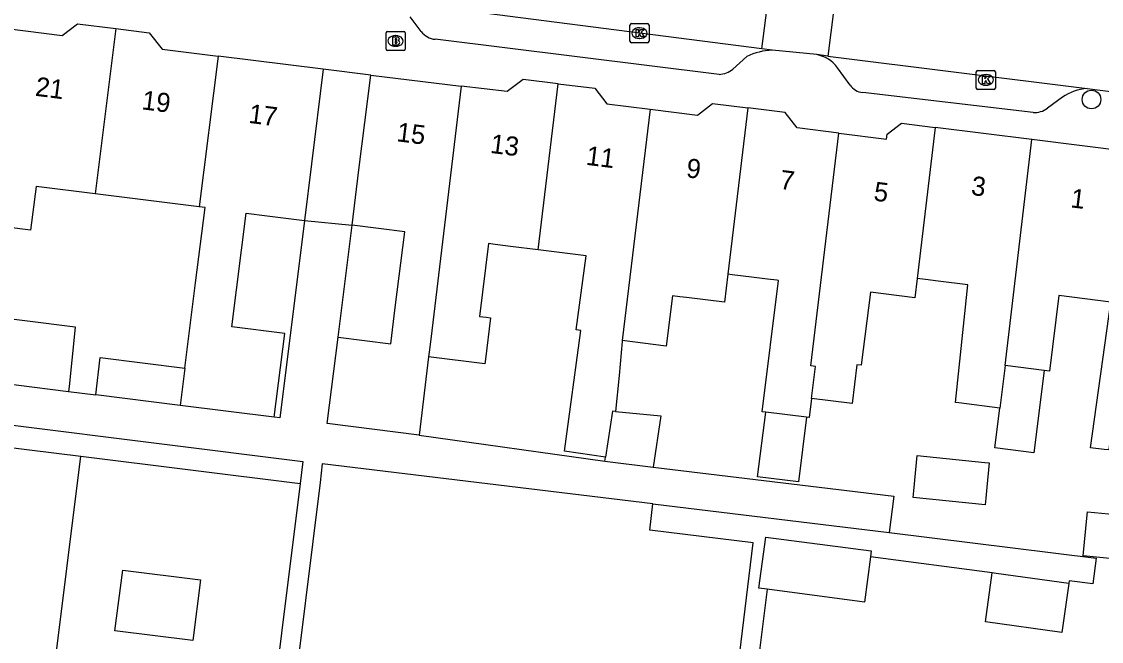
# Model space of a CAD drawing. Extents: x 161696 to 162377, y 380761 to 381673.
# Drawn here: x 162038 to 162094.7, y 381365 to 381397.5 of the extents above; entities that cross this region are included whole.
import ezdxf

# ---------------------------------------------------------------- set-up
doc = ezdxf.new("R2010")
doc.units = 0
for name, color, linetype in [('IMGEO_Boom', 7, 'Continuous'), ('IMGEO_Brandkraan', 7, 'Continuous'), ('IMGEO_Kolk', 7, 'Continuous'), ('IMGEO_Pand', 7, 'Continuous'), ('IMGEO_Pand_nummerreeks', 7, 'Continuous'), ('IMGEO_Pand_overbouw', 7, 'Continuous'), ('IMGEO_Rijbaan_lokaal_open', 7, 'Continuous'), ('IMGEO_Voetpad_open', 7, 'Continuous')]:
    doc.layers.add(name, color=color, linetype=linetype)

msp = doc.modelspace()

# ---------------------------------------------------------------- linework, layer by layer
at = {"layer": 'IMGEO_Boom'}
msp.add_circle((162094.154, 381393.439), 0.489, dxfattribs=at)
at = {"layer": 'IMGEO_Brandkraan'}
for p, q in [((162057.206, 381397.009), (162058.058, 381397.009)), ((162057.131, 381396.083), (162057.131, 381396.935)), ((162057.619, 381396.789), (162057.644, 381396.789)), ((162058.132, 381396.935), (162058.132, 381396.083)), ((162058.058, 381396.009), (162057.206, 381396.009)), ((162057.642, 381396.229), (162057.617, 381396.229))]:
    msp.add_line(p, q, dxfattribs=at)
for points in [[(162057.206, 381397.009), (162058.058, 381397.009)], [(162057.131, 381396.083), (162057.131, 381396.935)], [(162057.479, 381396.709), (162057.479, 381396.309), (162057.692, 381396.309)], [(162057.71, 381396.709), (162057.479, 381396.709)], [(162057.658, 381396.628), (162057.604, 381396.628), (162057.604, 381396.552)], [(162057.604, 381396.552), (162057.657, 381396.552)], [(162057.666, 381396.476), (162057.604, 381396.476), (162057.604, 381396.395)], [(162058.132, 381396.935), (162058.132, 381396.083)], [(162058.058, 381396.009), (162057.206, 381396.009)], [(162057.604, 381396.395), (162057.666, 381396.395)]]:
    msp.add_lwpolyline(points, dxfattribs=at)
for centre, radius, start, end in [((162057.208, 381396.933), 0.0765, 91.552, 178.448), ((162057.208, 381396.933), 0.0765, 91.552, 178.448), ((162058.056, 381396.933), 0.0765, 1.552, 88.448), ((162058.056, 381396.933), 0.0765, 1.552, 88.448), ((162057.659, 381396.59), 0.0379, 267.8285, 90.9355), ((162057.667, 381396.435), 0.0404, 269.8759, 90.5077), ((162057.714, 381396.564), 0.145, 59.4692, 91.5367), ((162057.739, 381396.611), 0.0922, 285.5137, 58.1501), ((162057.744, 381396.419), 0.105, 301.3115, 78.989), ((162057.208, 381396.085), 0.0765, 181.552, 268.448), ((162057.208, 381396.085), 0.0765, 181.552, 268.448), ((162057.698, 381396.56), 0.251, 268.6676, 293.5347), ((162058.056, 381396.085), 0.0765, 271.552, 358.448), ((162058.056, 381396.085), 0.0765, 271.552, 358.448)]:
    msp.add_arc(centre, radius, start, end, dxfattribs=at)
for centre, major_axis, ratio, start_param, end_param in [((162057.618, 381396.509), (-0.387, 0.002), 0.722429, 4.712389, 7.853982), ((162057.643, 381396.509), (-0.39, 0.002), 0.717154, 1.570796, 4.712389)]:
    msp.add_ellipse(centre, major_axis=major_axis, ratio=ratio, start_param=start_param, end_param=end_param, dxfattribs=at)
at = {"layer": 'IMGEO_Kolk'}
for p, q in [((162069.932, 381396.494), (162069.932, 381397.346)), ((162070.007, 381397.42), (162070.859, 381397.42)), ((162070.42, 381397.2), (162070.445, 381397.2)), ((162070.933, 381397.346), (162070.933, 381396.494)), ((162070.859, 381396.42), (162070.007, 381396.42)), ((162070.443, 381396.64), (162070.418, 381396.64)), ((162088.108, 381394.041), (162088.108, 381394.893)), ((162088.183, 381394.967), (162089.035, 381394.967)), ((162088.596, 381394.747), (162088.621, 381394.747)), ((162089.109, 381394.893), (162089.109, 381394.041)), ((162088.619, 381394.187), (162088.594, 381394.187)), ((162089.035, 381393.967), (162088.183, 381393.967))]:
    msp.add_line(p, q, dxfattribs=at)
for points in [[(162069.932, 381396.494), (162069.932, 381397.346)], [(162070.007, 381397.42), (162070.859, 381397.42)], [(162070.253, 381397.12), (162070.376, 381397.12), (162070.376, 381396.969), (162070.506, 381397.12), (162070.67, 381397.12), (162070.524, 381396.969), (162070.677, 381396.72), (162070.525, 381396.72), (162070.44, 381396.884), (162070.376, 381396.817), (162070.376, 381396.72), (162070.253, 381396.72), (162070.253, 381397.12)], [(162070.933, 381397.346), (162070.933, 381396.494)], [(162070.859, 381396.42), (162070.007, 381396.42)], [(162088.108, 381394.041), (162088.108, 381394.893)], [(162088.183, 381394.967), (162089.035, 381394.967)], [(162089.109, 381394.893), (162089.109, 381394.041)], [(162088.429, 381394.667), (162088.552, 381394.667), (162088.552, 381394.516), (162088.682, 381394.667), (162088.846, 381394.667), (162088.7, 381394.516), (162088.853, 381394.267), (162088.701, 381394.267), (162088.616, 381394.431), (162088.552, 381394.364), (162088.552, 381394.267), (162088.429, 381394.267), (162088.429, 381394.667)], [(162089.035, 381393.967), (162088.183, 381393.967)]]:
    msp.add_lwpolyline(points, dxfattribs=at)
for centre, start, end in [((162070.009, 381397.344), 91.552, 178.448), ((162070.009, 381397.344), 91.552, 178.448), ((162070.857, 381397.344), 1.552, 88.448), ((162070.857, 381397.344), 1.552, 88.448), ((162070.009, 381396.496), 181.552, 268.448), ((162070.009, 381396.496), 181.552, 268.448), ((162070.857, 381396.496), 271.552, 358.448), ((162070.857, 381396.496), 271.552, 358.448), ((162088.185, 381394.891), 91.552, 178.448), ((162088.185, 381394.891), 91.552, 178.448), ((162089.033, 381394.891), 1.552, 88.448), ((162089.033, 381394.891), 1.552, 88.448), ((162088.185, 381394.043), 181.552, 268.448), ((162088.185, 381394.043), 181.552, 268.448), ((162089.033, 381394.043), 271.552, 358.448), ((162089.033, 381394.043), 271.552, 358.448)]:
    msp.add_arc(centre, 0.0765, start, end, dxfattribs=at)
for centre, major_axis, ratio, start_param, end_param in [((162070.419, 381396.92), (-0.387, 0.002), 0.722429, 4.712389, 7.853982), ((162070.444, 381396.92), (-0.39, 0.002), 0.717154, 1.570796, 4.712389), ((162088.595, 381394.467), (-0.387, 0.002), 0.722429, 4.712389, 7.853982), ((162088.62, 381394.467), (-0.39, 0.002), 0.717154, 1.570796, 4.712389)]:
    msp.add_ellipse(centre, major_axis=major_axis, ratio=ratio, start_param=start_param, end_param=end_param, dxfattribs=at)
at = {"layer": 'IMGEO_Pand'}
for points in [[(162037.258, 381397.157), (162040.14, 381396.796), (162040.934, 381397.414), (162042.957, 381397.161)], [(162042.957, 381397.161), (162041.873, 381388.497)], [(162042.957, 381397.161), (162044.707, 381396.942), (162045.375, 381396.083), (162048.318, 381395.715)], [(162048.318, 381395.715), (162047.329, 381387.815)], [(162053.837, 381395.025), (162048.318, 381395.715)], [(162053.837, 381395.025), (162053.217, 381390.064), (162052.846, 381387.092)], [(162055.349, 381386.844), (162055.712, 381389.749), (162056.334, 381394.724)], [(162056.334, 381394.724), (162061.073, 381394.148)], [(162061.073, 381394.148), (162059.478, 381380.88), (162059.395, 381380.187), (162059.366, 381379.944)], [(162066.17, 381394.266), (162064.325, 381394.497), (162063.497, 381393.853), (162061.073, 381394.148)], [(162065.123, 381385.556), (162066.17, 381394.266)], [(162066.17, 381394.266), (162068.087, 381394.027), (162068.721, 381393.212), (162070.989, 381392.928)], [(162070.989, 381392.928), (162073.477, 381392.617), (162074.272, 381393.236), (162076.123, 381393.005)], [(162076.123, 381393.005), (162075.075, 381384.281)], [(162080.896, 381391.674), (162078.704, 381391.948), (162078.072, 381392.761), (162076.123, 381393.005)], [(162070.989, 381392.928), (162069.531, 381380.796)], [(162080.896, 381391.674), (162083.4, 381391.361), (162083.433, 381391.621), (162084.178, 381392.2), (162085.954, 381391.978)], [(162085.954, 381391.978), (162085.002, 381384.057)], [(162091.014, 381391.346), (162085.954, 381391.978)], [(162079.463, 381377.766), (162079.664, 381379.438), (162079.429, 381379.468), (162080.896, 381391.674)], [(162089.615, 381379.488), (162091.014, 381391.346)], [(162096.159, 381390.703), (162091.014, 381391.346)], [(162041.873, 381388.497), (162038.763, 381388.886), (162038.476, 381386.593), (162035.975, 381386.905)], [(162047.329, 381387.815), (162041.873, 381388.497)], [(162046.578, 381379.349), (162047.138, 381383.826), (162047.632, 381387.777), (162047.329, 381387.815)], [(162051.269, 381376.783), (162051.817, 381381.17), (162049.04, 381381.518), (162049.785, 381387.474), (162050.065, 381387.439), (162050.622, 381387.37), (162052.846, 381387.092)], [(162054.615, 381380.971), (162057.377, 381380.626), (162057.615, 381382.534), (162058.11, 381386.499), (162055.349, 381386.844)], [(162065.123, 381385.556), (162063.658, 381385.739), (162062.866, 381385.838), (162062.508, 381385.883), (162062.03, 381382.063), (162062.389, 381382.018), (162062.617, 381381.99), (162062.345, 381379.818), (162062.315, 381379.575), (162059.366, 381379.944)], [(162068.648, 381374.686), (162066.5, 381374.99), (162067.356, 381381.329), (162067.108, 381381.362), (162067.631, 381385.243), (162065.123, 381385.556)], [(162075.075, 381384.281), (162074.898, 381382.806), (162072.902, 381383.055), (162072.542, 381383.1), (162072.17, 381383.146), (162071.839, 381380.507), (162069.531, 381380.796)], [(162077.057, 381377.042), (162076.872, 381377.065), (162077.734, 381383.949), (162077.648, 381383.96), (162077.156, 381384.021), (162076.306, 381384.127), (162075.302, 381384.253), (162075.075, 381384.281)], [(162085.002, 381384.057), (162084.88, 381383.044), (162082.549, 381383.335), (162082.07, 381379.502), (162081.844, 381379.53), (162081.59, 381377.5), (162079.463, 381377.766)], [(162089.337, 381377.258), (162087.19, 381377.526), (162087.011, 381377.548), (162087.657, 381383.726), (162086.102, 381383.92), (162085.446, 381384.002), (162085.002, 381384.057)], [(162095.173, 381382.813), (162092.436, 381383.155), (162091.941, 381379.198), (162091.666, 381379.232)], [(162035.369, 381382.094), (162035.381, 381382.2), (162040.822, 381381.513), (162040.79, 381381.146), (162040.496, 381378.382), (162040.469, 381378.131)], [(162058.873, 381375.843), (162054.049, 381376.446), (162054.615, 381380.971)], [(162069.531, 381380.796), (162069.526, 381380.753), (162069.358, 381378.97), (162069.175, 381377.081)], [(162041.894, 381377.954), (162042.137, 381379.904), (162046.578, 381379.349)], [(162059.366, 381379.944), (162058.873, 381375.843)], [(162089.615, 381379.488), (162089.337, 381377.258)], [(162091.666, 381379.232), (162089.615, 381379.488)], [(162046.578, 381379.349), (162046.334, 381377.399)], [(162091.666, 381379.232), (162091.127, 381374.909), (162089.076, 381375.166), (162089.337, 381377.258)], [(162034.963, 381378.819), (162040.469, 381378.131)], [(162046.334, 381377.399), (162041.894, 381377.954)], [(162079.463, 381377.766), (162079.338, 381376.757), (162079.2, 381376.774)], [(162051.269, 381376.783), (162046.334, 381377.399)], [(162069.175, 381377.081), (162069.008, 381377.097), (162068.648, 381374.686)], [(162069.175, 381377.081), (162071.545, 381376.858), (162071.151, 381374.15)], [(162079.2, 381376.774), (162078.776, 381373.384), (162076.633, 381373.652), (162077.057, 381377.042)], [(162079.2, 381376.774), (162077.057, 381377.042)], [(162034.803, 381369.197), (162035.577, 381375.42), (162041.121, 381374.73)], [(162038.184, 381351.173), (162041.121, 381374.73)], [(162041.121, 381374.73), (162052.623, 381373.299)], [(162068.615, 381374.467), (162068.648, 381374.686)], [(162068.615, 381374.467), (162071.151, 381374.15)], [(162088.553, 381374.412), (162088.79, 381374.388), (162088.661, 381373.107), (162088.603, 381372.529), (162088.568, 381372.189), (162084.79, 381372.569), (162084.824, 381372.91), (162085.012, 381374.77), (162088.553, 381374.412)], [(162052.623, 381373.299), (162050.669, 381357.597), (162050.309, 381354.704), (162049.692, 381349.742)], [(162096.886, 381371.529), (162096.852, 381371.178), (162096.818, 381370.826), (162096.663, 381369.223), (162096.528, 381369.236), (162093.712, 381369.509), (162093.92, 381371.655), (162093.935, 381371.815), (162096.886, 381371.529)], [(162077.135, 381367.757), (162076.704, 381367.814), (162077.055, 381370.489), (162082.588, 381369.763), (162082.547, 381369.454)], [(162082.547, 381369.454), (162082.237, 381367.087), (162077.135, 381367.757)], [(162047.399, 381368.243), (162046.995, 381365.06), (162042.893, 381365.569), (162043.312, 381368.754), (162047.399, 381368.243)], [(162092.955, 381368.064), (162092.6, 381365.486), (162088.584, 381366.04), (162088.939, 381368.617)], [(162092.955, 381368.064), (162089.151, 381368.588), (162088.939, 381368.617)]]:
    msp.add_lwpolyline(points, dxfattribs=at)
at = {"layer": 'IMGEO_Pand_overbouw'}
msp.add_lwpolyline([(162056.334, 381394.724), (162053.837, 381395.025), (162053.217, 381390.064), (162052.846, 381387.092), (162055.349, 381386.844), (162055.712, 381389.749)], close=True, dxfattribs=at)
at = {"layer": 'IMGEO_Rijbaan_lokaal_open'}
for points in [[(162076.85, 381396.098), (162077.323, 381399.762)], [(162080.767, 381399.306), (162080.312, 381395.719)], [(162076.85, 381396.098), (162057.242, 381398.61)], [(162077.396, 381396.028), (162076.85, 381396.098)], [(162079.731, 381395.792), (162077.396, 381396.028)], [(162080.312, 381395.719), (162079.731, 381395.792)], [(162080.312, 381395.719), (162093.918, 381394.013)], [(162093.918, 381394.013), (162096.927, 381393.631)]]:
    msp.add_lwpolyline(points, dxfattribs=at)
at = {"layer": 'IMGEO_Voetpad_open'}
for points in [[(162058.983, 381397), (162058.392, 381397.782)], [(162074.61, 381394.751), (162059.711, 381396.598)], [(162076.066, 381395.693), (162075.336, 381395.039)], [(162056.334, 381394.724), (162053.837, 381395.025)], [(162081.486, 381394.196), (162080.823, 381395.107)], [(162091.084, 381392.754), (162082.146, 381393.802)], [(162092.628, 381393.562), (162091.845, 381392.98)], [(162052.846, 381387.092), (162052.128, 381381.351), (162051.552, 381376.748), (162051.269, 381376.783)], [(162054.615, 381380.971), (162055.349, 381386.844)], [(162095.86, 381381.582), (162095.063, 381375.06), (162094.826, 381375.089), (162094.098, 381375.165), (162095.173, 381382.813)], [(162040.469, 381378.131), (162041.894, 381377.954)], [(162029.846, 381377.326), (162052.767, 381374.449), (162052.623, 381373.299)], [(162058.873, 381375.843), (162068.615, 381374.467)], [(162071.138, 381372.231), (162053.786, 381374.326), (162053.669, 381373.359), (162052.113, 381360.842), (162052.1, 381360.737)], [(162071.151, 381374.15), (162083.774, 381372.644), (162083.528, 381370.735)], [(162074.51, 381354.62), (162076.391, 381370.198), (162070.971, 381370.852), (162071.138, 381372.231)], [(162071.138, 381372.231), (162083.528, 381370.735)], [(162083.528, 381370.735), (162094.392, 381369.392), (162094.229, 381368.044), (162092.973, 381368.195), (162092.955, 381368.064)], [(162088.939, 381368.617), (162082.547, 381369.454)], [(162077.135, 381367.757), (162076.421, 381362.024)]]:
    msp.add_lwpolyline(points, dxfattribs=at)
for centre, radius, start, end in [((162059.783, 381397.588), 0.992, 216.3241, 265.8611), ((162077.525, 381392.708), 3.322, 92.2252, 116.0499), ((162079.433, 381394.104), 1.714, 35.8083, 79.9925), ((162074.541, 381395.985), 1.236, 273.217, 310.0589), ((162082.238, 381394.706), 0.909, 214.1554, 264.1728), ((162094.14, 381391.309), 2.713, 94.6838, 123.8567), ((162091.127, 381394.003), 1.25, 268.024, 305.0565)]:
    msp.add_arc(centre, radius, start, end, dxfattribs=at)

# ---------------------------------------------------------------- texts
at = {"layer": 'IMGEO_Pand_nummerreeks'}
for s, rotation, p in [('21', 352.7701, (162038.689, 381393.641)), ('19', 352.7701, (162044.278, 381392.931)), ('17', 352.7693, (162049.888, 381392.219)), ('15', 352.924, (162057.656, 381391.254)), ('13', 352.924, (162062.568, 381390.644)), ('11', 352.924, (162067.593, 381390.02)), ('9', 352.924, (162072.85, 381389.368)), ('7', 352.924, (162077.762, 381388.758)), ('5', 352.8724, (162082.689, 381388.144)), ('3', 352.8781, (162087.803, 381388.441)), ('1', 352.8781, (162093.019, 381387.79))]:
    msp.add_text(s, height=1, rotation=rotation, dxfattribs=at).set_placement(p)

doc.saveas('drawing.dxf')
